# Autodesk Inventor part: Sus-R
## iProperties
Created: 2007-12
Part Number: Sus-R
Document SubType Name: Modeling
Designer: UJA2299
Density: 1 g/cm^3
Author: UJA2299
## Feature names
1. 回転1 [Revolution]
2. シェル1
3. 押し出し1 [Extrusion]
4. 押し出し2 [Extrusion]
